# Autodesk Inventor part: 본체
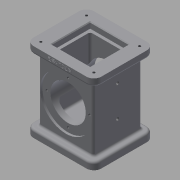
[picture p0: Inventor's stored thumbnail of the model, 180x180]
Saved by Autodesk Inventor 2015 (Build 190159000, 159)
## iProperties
Created: 2017-08
Part Number: 본체
Material: 일반
Document SubType Name: Modeling
Designer: Administrator
Density: 1 g/cm^3
Appearance: 기본값
Author: Administrator
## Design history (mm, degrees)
sketch "스케치1"
  geometry: L1 (-46, 41)-(46, 41); L2 (46, 41)-(46, -41); L3 (46, -41)-(-46, -41); L4 (-46, -41)-(-46, 41); L5 (46, -41)-(-46, 41); 2 further points
  constraints: 10 end point, 2 parallel, 1 coincident, 1 horizontal, 1 midpoint, 1 perpendicular
  dimensions: "d0" = 92 distance of L1.start L1.end; "d1" = 82 distance of L3.end L1.start
extrude "돌출1" new body sketch "스케치1" distance "d2" = 10; taper "d3" = 0 deg
sketch "스케치2"
  geometry: L1 (-37, 33)-(37, 33); L2 (37, 33)-(37, -33); L3 (37, -33)-(-37, -33); L4 (-37, -33)-(-37, 33); L5 (37, -33)-(-37, 33); 2 further points
  constraints: 10 end point, 2 parallel, 1 coincident, 1 horizontal, 1 midpoint, 1 perpendicular
  dimensions: "d4" = 74 distance of L1.start L1.end; "d5" = 66 distance of L1.end L2.end
extrude "돌출2" join sketch "스케치2" distance "d6" = 88; taper "d7" = 0 deg
sketch "스케치3"
  geometry: L1 (37, 33)-(37, -33) reference; L2 (37, -33)-(-37, -33) reference; L3 (-37, -33)-(-37, 33) reference; L4 (-37, 33)-(37, 33) reference; L5 (46, 41)-(-46, 41) reference; L6 (-46, 41)-(-46, -41) reference; L7 (-46, -41)-(46, -41) reference; L8 (46, -41)-(46, 41) reference; 1 further point
extrude "돌출3" join sketch "스케치3" distance "d8" = 10; taper "d9" = 0 deg
sketch "스케치4"
  geometry: L1 (24, -24)-(-24, -24); L2 (-24, -24)-(-24, 24); L3 (-24, 24)-(24, 24); L4 (24, 24)-(24, -24); L5 (-24, 24)-(24, -24); 2 further points
  constraints: 10 end point, 2 parallel, 2 perpendicular, 1 coincident, 1 horizontal, 1 midpoint
  dimensions: "d10" = 48 distance of L1.start L1.end
extrude "돌출4" cut sketch "스케치4" distance "d11" = 16; taper "d12" = 0 deg
sketch "스케치6"
  geometry: L1 (37, -10)-(37, 44); 1 further point
  constraints: 2 end point, 1 coincident, 1 vertical
  dimensions: "d48" = 54 distance of L1.start L1.end
hole "구멍1" sketch "스케치6" at (37, 44) diameter "d15" = 48; stored, may be unused: countersink angle "d19" = 90 deg, drill point angle "d21" = 118 deg; dims "d16" = 6, "d17" = 4, "d18" = 2, "d20" = 8
hole "구멍2" diameter "d24" = 70; stored, may be unused: countersink angle "d28" = 90 deg, drill point angle "d30" = 0 deg; dims "d25" = 6, "d26" = 4, "d27" = 2, "d29" = 3, "d35" = 10, "d36" = 10
sketch "스케치5"
  geometry: L1 (-22, 22)-(22, 22); L2 (22, 22)-(22, -22); L3 (22, -22)-(-22, -22); L4 (-22, -22)-(-22, 22); L5 (-26, 26)-(26, 26); L6 (26, 26)-(26, -26); L7 (26, -26)-(-26, -26); L8 (-26, -26)-(-26, 26); L9 (26, -26)-(-26, 26); L10 (22, -22)-(-22, 22); 2 further points
  constraints: 20 end point, 4 parallel, 3 perpendicular, 2 horizontal, 2 midpoint, 1 coincident, 1 collinear
  dimensions: "d13" = 52 distance of L5.start L5.end; "d14" = 44 distance of L1.start L1.end
extrude "돌출5" cut sketch "스케치5" distance "d33" = 82; taper "d34" = 0 deg
extrude "돌출6" cut sketch "스케치5" distance "d37" = 8; taper "d38" = 0 deg
sketch "스케치7"
  geometry: L1 (-36, 31)-(36, 31); L2 (36, 31)-(36, -31); L3 (36, -31)-(-36, -31); L4 (-36, -31)-(-36, 31); L5 (36, -31)-(-36, 31); 6 further points
  constraints: 10 end point, 5 coincident, 2 parallel, 1 horizontal, 1 midpoint, 1 perpendicular
  dimensions: "d39" = 72 distance of L1.start L1.end; "d40" = 62 distance of L1.end L2.end
hole "구멍3" sketch "스케치7" at (-36, 31), (36, 31), (-36, -31), (36, -31) diameter "d41" = 3.242; stored, may be unused: countersink angle "d45" = 90 deg, drill point angle "d47" = 118 deg; dims "d42" = 4, "d43" = 4, "d44" = 2, "d46" = 6
node "작업 평면1"
sketch "스케치8"
  geometry: C1 r 35 at (0, 0) reference; A1 r 29 centre (0, 0) between (0, 29) and (-29, 0); 3 further points
  constraints: 4 point on circle, 2 horizontal alignment, 2 vertical alignment, 1 centre point, 1 coincident
  dimensions: "d49" = 58 diameter of A1
hole "구멍4" sketch "스케치8" at (0, 29), (-29, 0), (0, -29), (29, 0) diameter "d50" = 3.242; stored, may be unused: countersink angle "d54" = 90 deg, drill point angle "d56" = 118 deg; dims "d51" = 4, "d52" = 4, "d53" = 2, "d55" = 6
sketch "스케치9"
  geometry: L1 (10, 33)-(-70, 33); 2 further points
  constraints: 2 end point, 1 coincident, 1 horizontal, 1 point on line
  dimensions: "d57" = 38 distance of point (-28, 33) L1.start; "d58" = 42 distance of point (-70, 33) point (-28, 33)
hole "구멍5" sketch "스케치9" at (-28, 33), (-70, 33) diameter "d65" = 4.134; stored, may be unused: countersink angle "d69" = 90 deg, drill point angle "d71" = 118 deg; dims "d66" = 10, "d67" = 4, "d68" = 2, "d70" = 20
fillet "모깎기1" dims "d59" = 10
fillet "모깎기2" dims "d60" = 3
fillet "모깎기3" dims "d61" = 3
chamfer "모따기1" distance "d62" = 1; stored, may be unused: second distance "d63" = 2, angle "d64" = 45 deg
node "작업 평면2"
sketch "스케치10"
  geometry: L1 (12.716, -0.432)-(59.284, -0.432); L2 (59.284, -0.432)-(59.284, -7.568); L3 (59.284, -7.568)-(12.716, -7.568); L4 (12.716, -7.568)-(12.716, -0.432); L5 (12.716, -0.432)-(59.284, -7.568); L6 (0, 0)-(72, 0) reference; 3 further points
  constraints: 2 end point, 2 midpoint, 1 vertical alignment, 2 other
  dimensions: "d73" = 4 distance from line of point (36, -4) L6
feature "엠보싱1" sketch "스케치10" dims "d0" = 92, "d1" = 82, "d74" = 0.5, "d75" = 0
node "솔리드1"
mirror "대칭1"
mirror "대칭2"
mirror "대칭3"
node "투영된 루프1"
other parameters: "d72" = 18.75
